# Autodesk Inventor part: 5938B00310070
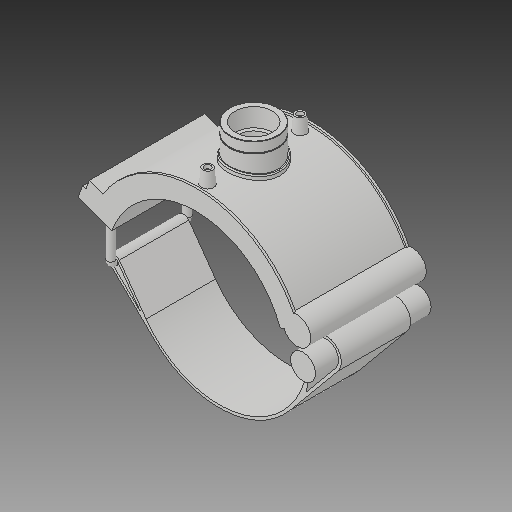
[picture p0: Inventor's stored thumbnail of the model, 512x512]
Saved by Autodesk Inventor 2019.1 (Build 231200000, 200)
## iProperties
Created: 2017-07
Part Number: 5938B00310070
Material: Generic
Description: PLASSON TRANSITION SADDLE 10''IPS x 2"NPT
Document SubType Name: Modeling
Designer: KIM
Density: 1 g/cm^3
Appearance: Default
Author: KIM
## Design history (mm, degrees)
derived "5938B.ipt"
feature "Solid1::5938B.ipt"
tag "TaggingFeature1"
body "Solid1"
other parameters: "d0" = 272.7, "d1" = 327.24, "d2" = 450.85, "d3" = 68.175, "d4" = 176.022, "d5" = 0, "d40" = 170.1648, "d41" = 79.3184, "d43" = 0, "d45" = 0, "d47" = 210.356, "d48" = 73.6528, "d50" = 0, "d78" = 185.62, "d79" = 15, "d80" = 70.4088, "d82" = 5 deg, "d84" = 4, "d85" = 14, "d86" = 0, "d87" = 3, "d88" = 0, "d96" = 333.7848, "d97" = 3.52044, "d98" = 0, "d102" = 1.69968, "d103" = 56.656, "d104" = 28.0416, "d105" = 0, "d106" = 45.3248, "d108" = 0, "d109" = -15.57867, "d111" = 0.5, "d112" = 0.5, "d113" = 0, "d114" = 0.5, "d117" = 0.56656, "d120" = 140 deg, "d121" = 24.228, "d122" = 20 deg, "d123" = 1308.96, "d124" = 196.344, "d126" = 0, "d143" = 280.881, "d145" = 41.95385, "d149" = 4.0905, "d150" = 46.14923, "d153" = 176.022, "d154" = 0, "d156" = 163.62, "d157" = 160 deg, "d159" = 10.908, "d161" = 4.0905, "d162" = 105.6132, "d163" = 0, "d164" = 136.35, "d167" = 27.27, "d168" = 159.62927, "d170" = 4.0905, "d172" = 0, "d173" = 1, "d175" = 136.35, "d176" = 20 deg, "d177" = 19.089, "d178" = 54.54, "d180" = 0, "d183" = 21.816, "d184" = 15.2712, "d185" = 57.20715, "d186" = 57.20715, "d187" = 163.62, "d188" = 16.362, "d189" = 19.089, "d190" = 0, "d191" = 196.344, "d193" = 10.908, "d194" = 5.59035, "d195" = 90 deg, "d197" = 0, "d199" = 0, "d_" = 272.7, "B_" = 180.34, "H_" = 46.736, "L_" = 176.022, "d_t" = 6, "G_" = 56.656, "d148" = 4.0905, "d160" = 4.0905, "d169" = 4.0905, "d192" = 10.908
